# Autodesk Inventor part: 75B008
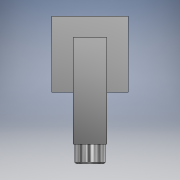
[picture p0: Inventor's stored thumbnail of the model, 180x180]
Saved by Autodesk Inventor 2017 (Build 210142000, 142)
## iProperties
Created: 2022-02
Part Number: 75B008
Material: Generico
Document SubType Name: Modeling
Designer: CIANI
Density: 1 g/cm^3
Appearance: Default
Author: CIANI
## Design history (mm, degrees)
feature "Base1"
node "Solido1"
node "Solido2"
